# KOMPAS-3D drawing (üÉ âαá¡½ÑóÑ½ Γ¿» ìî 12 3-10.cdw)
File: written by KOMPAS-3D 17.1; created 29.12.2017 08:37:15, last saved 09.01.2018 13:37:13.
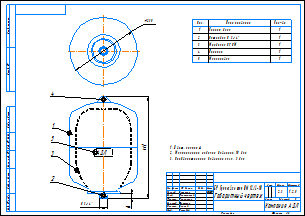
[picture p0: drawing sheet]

Sheet 1: A3, landscape, title-block layout from C:\Лощинин\GRAPHIC.LYT style 1

Title block, sheet 1: name: БР Гранлевел тип НМ 12/3-10 / Габаритный чертеж; mass: 2,3; scale: 1:2,5; sheets: 1; sheet format: A3; stored path: K:\АП\20_PKO\02_Насосное направление\Разработка\04_Проекты разные\Баки\КД действующая\Баки Flexcon R\Компас\Чертежи\БР Гранлевел тип НМ 12 1,5-6.cdw; drawn by: Лощинин; checked by: Хантимеров; drawn by, date: 29.12.2017

Views: Проекционный вид 2
Referenced files in \\Fsk1\files\АП\20_PKO\02_Насосное направление\Разработка\04_Проекты разные\Баки\КД действующая\Баки Flexcon R\Компас\: 12 литров.a3d
Referenced files in C:\Лощинин\: GRAPHIC.LYT
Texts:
  IvAn
  ADL
  БР Гранлевел тип НМ 12/1,5-6
  Цвет: красный
  Максимальное рабочее давление: 10 бар
  Предварительное давление газа: 3 бар
  Лит-Масса-Масштаб
  Материал-Предприятие
  Масштаб
  Изм.
  Лист
  № докум.
  Подп.
  Дата
  Лит.
  Разраб.
  Пров.
  Т.контр.
  Курлыкина
  Листов
  Нач.отд.
  Щетинин
  Н.контр.
  Долгов
  Утв.
  Рашидов
  Компания АДЛ
  Изменение
  Номер документа
  Подпись
  Обозначение документа
  Наименование изделия
  Масса изделия по ГОСТ 2.109-73
  Порядковый номер листа
  Общее количество листов в документе
  Характер работы, выполненной лицом, подписавшим документ
  Наименование или индекс предприятия, выпускающего документ
  Инв. № подл.
  Подп. и дата
  Взам. инв. №
  Инв. № дубл.
  Инвентарный номер подлинника по ГОСТ 2.501-68
  Подпись принявшего подлинник в отдел технической документации
  Инвентарный номер подлинника, взамен которого выпущен данный подлинник
  Инвентарный номер дубликата по ГОСТ 2.502-68
  Подпись принявшего дубликат в отдел технической документации
  Справ. №
  Перв. примен.
  Обозначение документа, взамен или на основании которого выпущен данный документ
  Обозначение документа, в котором впервые записан данный документ
  Подпись лица, копировавшего чертеж
  Обозначение формата листа
Dimensions and other numbers on the sheet: 235; 1:2,5; 1; 2,3; 29.12.2017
